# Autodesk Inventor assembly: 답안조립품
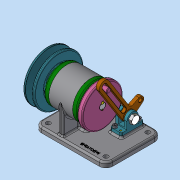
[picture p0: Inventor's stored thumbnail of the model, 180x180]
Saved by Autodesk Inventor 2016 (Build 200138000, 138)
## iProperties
Created: 2019-09
Part Number: 답안조립품
Material: 일반
Document SubType Name: Assembly
Designer: Administrator
Author: Administrator
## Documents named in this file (19)
- C:\Users\Administrator\Desktop\390904V1044\답안조립품.iam
- C:\Users\Administrator\Desktop\390904V1044\본체.ipt
- C:\Users\Administrator\Desktop\390904V1044\베어링 6004.ipt
- C:\Users\Administrator\Desktop\390904V1044\커버.ipt
- C:\Users\Administrator\Desktop\390904V1044\축.ipt
- C:\Users\Administrator\Desktop\390904V1044\오일 실 17 30 5.ipt
- C:\Users\Administrator\Desktop\390904V1044\키 4 x 4 x 8.ipt
- C:\Users\Administrator\Desktop\390904V1044\돌림판.ipt
- C:\Users\Administrator\Desktop\390904V1044\멈춤나사 M3x5.ipt
- C:\Users\Administrator\Desktop\390904V1044\힌지.ipt
- C:\Users\Administrator\Desktop\390904V1044\핀 3 x 8.ipt
- C:\Users\Administrator\Desktop\390904V1044\크랭크.ipt
- C:\Users\Administrator\Desktop\390904V1044\힌지 축.ipt
- C:\Users\Administrator\Desktop\390904V1044\와셔 8x15.5.ipt
- C:\Users\Administrator\Desktop\390904V1044\너트 M10x1.ipt
- C:\Users\Administrator\Desktop\390904V1044\키 5 x 5 x 12.ipt
- C:\Users\Administrator\Desktop\390904V1044\V-벨트풀리.ipt
- C:\Users\Administrator\Desktop\390904V1044\볼트 M4.ipt
- C:\Users\Administrator\Desktop\390904V1044\너트 M8.ipt
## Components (3 placed, 2 different names)
1. 핀 3 x 8:1 — 플러쉬:1
2. 핀 3 x 8:2 — 플러쉬:2
3. V-벨트풀리:1
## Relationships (2: Flush 2)
- 플러쉬:1 [Flush]: 핀 3 x 8:1
- 플러쉬:2 [Flush]: 핀 3 x 8:2
